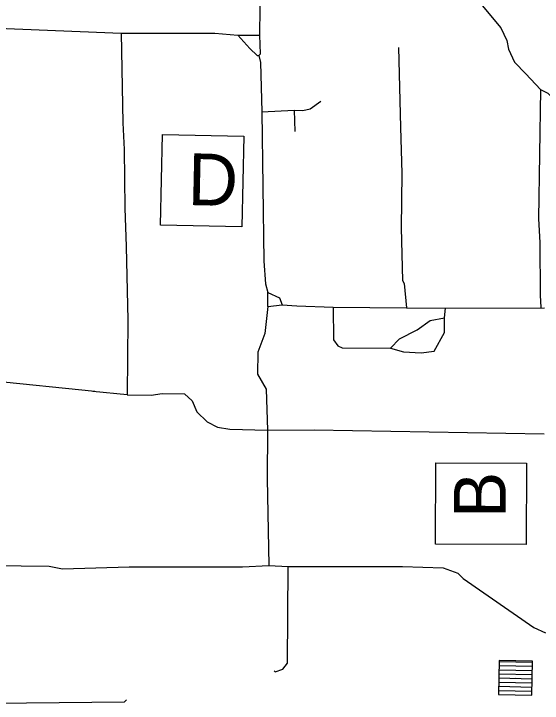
# Model space of a CAD drawing. Extents: x 299354 to 1325680, y 96128 to 228242.
# Drawn here: x 341858 to 352048, y 188409 to 201720 of the extents above; entities that cross this region are included whole.
import ezdxf

# ---------------------------------------------------------------- set-up
doc = ezdxf.new("R2010")
doc.units = 0
for name, color, linetype in [('Level 13', 7, 'Continuous'), ('Level 2', 7, 'Continuous'), ('Level 4', 7, 'Continuous'), ('Level 51', 7, 'Continuous')]:
    doc.layers.add(name, color=color, linetype=linetype)

msp = doc.modelspace()

# ---------------------------------------------------------------- linework, layer by layer
at = {"layer": 'Level 13'}
for p, q in [((345524, 198522), (345524, 198522)), ((350845, 192293), (350845, 192293))]:
    msp.add_line(p, q, dxfattribs=at)
for points in [[(344687, 197642), (344724, 199392), (346294, 199358), (346256, 197608)], [(351739, 191471), (349989, 191478), (349995, 193048), (351745, 193041)]]:
    msp.add_lwpolyline(points, close=True, dxfattribs=at)
at = {"layer": 'Level 2'}
for points in [[(341234, 201453), (343927, 201346)], [(343927, 201346), (345736, 201346), (346178, 201309)], [(346178, 201309), (346409, 201048), (346550, 200913), (346583, 200913)], [(346583, 200913), (346615, 200780), (346640, 199829)], [(346640, 199829), (346680, 196946), (346709, 196504), (346758, 196336)], [(346758, 196336), (346982, 196234), (347031, 196101)], [(347031, 196101), (347314, 196081), (348014, 196058)], [(348014, 196058), (349432, 196046)], [(349432, 196046), (350183, 196039)], [(350183, 196039), (352095, 196043)]]:
    msp.add_lwpolyline(points, dxfattribs=at)
at = {"layer": 'Level 4'}
msp.add_line((343384, 194437), (344046, 194367), dxfattribs=at)
for points in [[(346603, 201305), (346669, 206588)], [(350664, 203876), (350638, 202927), (350634, 202468), (350682, 202301), (350829, 201958), (351250, 201446), (351365, 201203), (351396, 201036), (351511, 200785), (351734, 200558), (352015, 200256)], [(343927, 201346), (343961, 199612), (343989, 199103), (343996, 197970), (344022, 197228), (344059, 195803), (344046, 194361)], [(346178, 201309), (346603, 201305)], [(346583, 200913), (346617, 200946), (346603, 201305)], [(349278, 201072), (349314, 199530)], [(352015, 200256), (351975, 197764), (352004, 197306), (352011, 196289), (352020, 196051)], [(352015, 200256), (352156, 200188), (352271, 200062), (352486, 199810), (352872, 199198), (353119, 198871), (353326, 198652), (353526, 198617), (354326, 198593)], [(347266, 199857), (347432, 199855), (347574, 199888), (347776, 200036)], [(346640, 199829), (347266, 199857)], [(347266, 199857), (347278, 199449)], [(349314, 199530), (349339, 198638)], [(349339, 198638), (349330, 197588), (349354, 196571), (349386, 196513), (349432, 196046)], [(346755, 196070), (346758, 196336)], [(346755, 196070), (346700, 195545), (346564, 195188), (346560, 194763), (346724, 194470), (346750, 193678)], [(346755, 196070), (347031, 196101)], [(348014, 196058), (348025, 195425), (348108, 195308), (348191, 195273), (349125, 195265)], [(350164, 195847), (350183, 196039)], [(349125, 195265), (349293, 195447), (349637, 195619), (349889, 195800), (350164, 195847)], [(349125, 195265), (349374, 195196), (349716, 195176), (349966, 195207), (350162, 195564), (350164, 195847)], [(341405, 194643), (343421, 194433)], [(344046, 194361), (344504, 194357), (344721, 194388), (345147, 194384), (345296, 194250), (345385, 194032), (345584, 193839), (345783, 193737), (346024, 193701), (346750, 193678)], [(346750, 193678), (346741, 192745), (346776, 191070)], [(346750, 193678), (347651, 193687), (352087, 193613)], [(341455, 191068), (342539, 191058), (342797, 191006), (344082, 191044)], [(344082, 191044), (346267, 191041), (346776, 191070)], [(346776, 191070), (347151, 191049)], [(346882, 189035), (346899, 189018), (347049, 189067), (347134, 189183), (347151, 191049)], [(347151, 191049), (349353, 191046)], [(349353, 191046), (350136, 191022), (350419, 190920), (350526, 190819), (351885, 189873), (352110, 189771)], [(341464, 188409), (343991, 188436), (344029, 188473)]]:
    msp.add_lwpolyline(points, dxfattribs=at)
at = {"layer": 'Level 51'}
for p, q in [((351219, 189216), (351863, 189202)), ((351215, 189056), (351860, 189042)), ((351217, 189136), (351862, 189122)), ((351212, 188896), (351857, 188882)), ((351213, 188976), (351858, 188962)), ((351525, 188904), (351525, 188904)), ((351210, 188816), (351855, 188802)), ((351206, 188656), (351851, 188642)), ((351208, 188736), (351853, 188722))]:
    msp.add_line(p, q, dxfattribs=at)
msp.add_lwpolyline([(351219, 189233), (351205, 188576), (351850, 188562), (351864, 189219)], close=True, dxfattribs=at)

# ---------------------------------------------------------------- texts
at = {"layer": 'Level 13'}
for s, rotation, p in [('D', 358.767, (345206, 198028)), ('B', 89.767, (351344, 191984))]:
    msp.add_text(s, height=1000, rotation=rotation, dxfattribs=at).set_placement(p)

doc.saveas('drawing.dxf')
